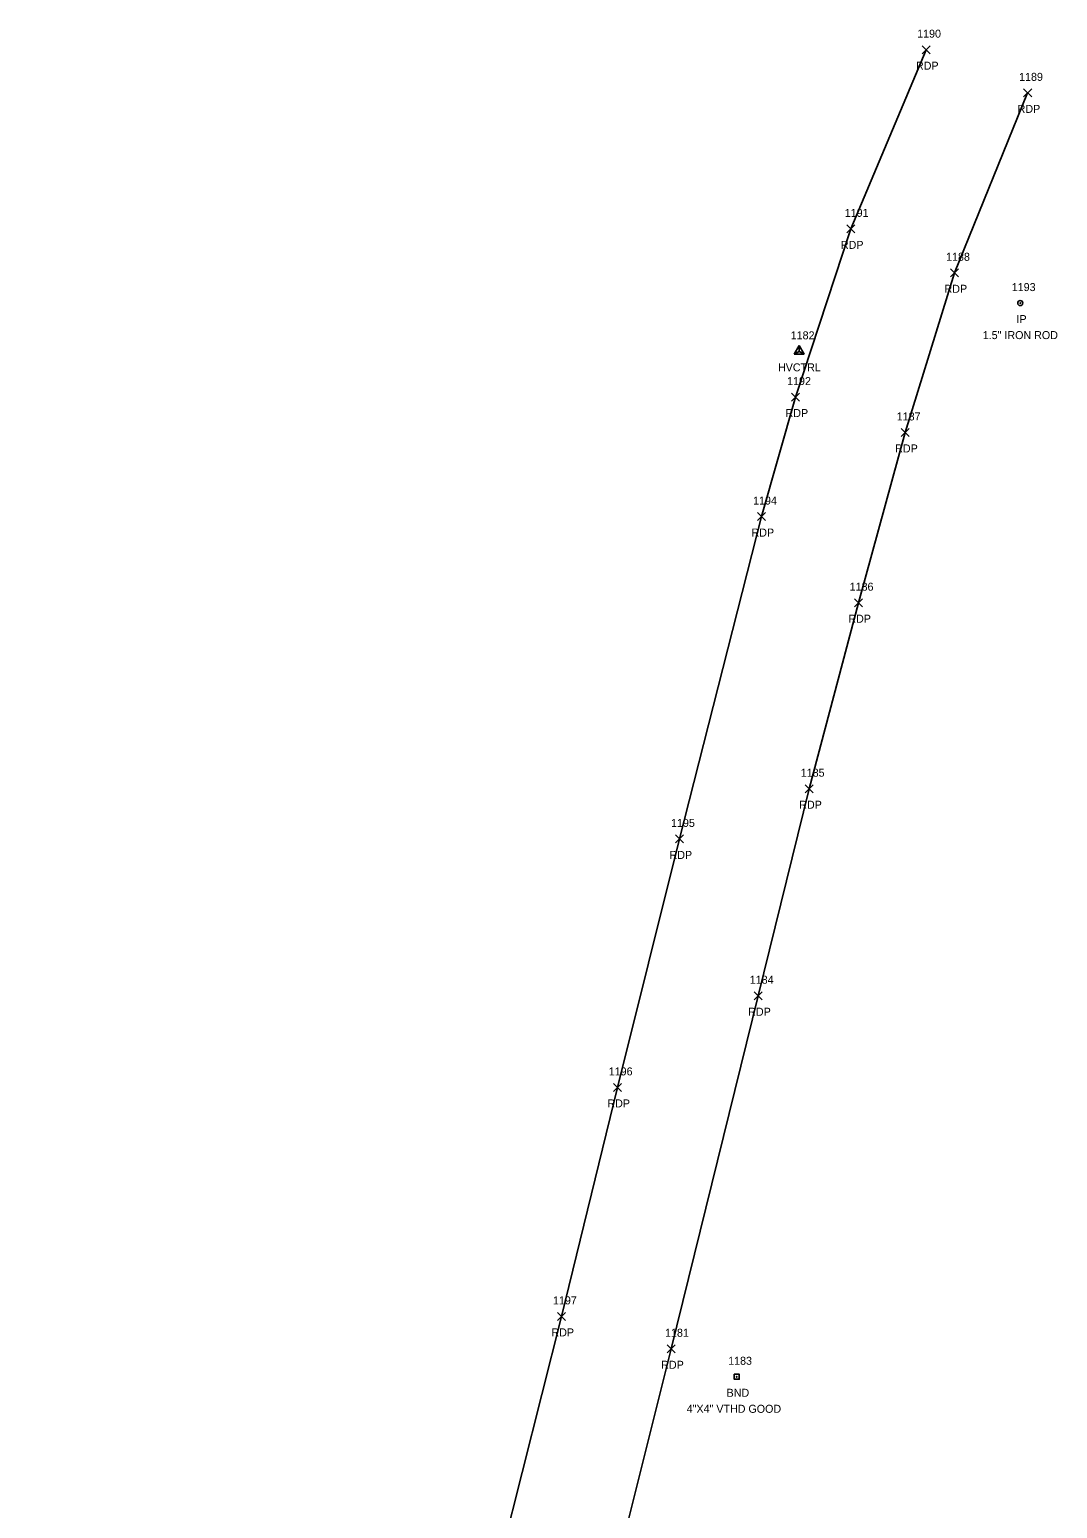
# Model space of a CAD drawing. Extents: x 1496556 to 1498241, y 599216 to 604470.
# Drawn here: x 1497984.6 to 1498241.4, y 604100.3 to 604469.9 of the extents above; entities that cross this region are included whole.
import ezdxf

# ---------------------------------------------------------------- set-up
doc = ezdxf.new("R2010")
doc.units = 0
for name, color, linetype in [('C_A', 7, 'Continuous'), ('C_I', 7, 'Continuous'), ('CPSM', 7, 'Continuous'), ('Level 18', 7, 'Continuous'), ('M_A', 7, 'Continuous'), ('M_C', 7, 'Continuous'), ('M_I', 7, 'Continuous'), ('MPIR', 7, 'Continuous'), ('P_A', 7, 'Continuous'), ('P_I', 7, 'Continuous'), ('P_TIC', 7, 'Continuous'), ('PET', 7, 'Continuous')]:
    doc.layers.add(name, color=color, linetype=linetype)

msp = doc.modelspace()

# ---------------------------------------------------------------- linework, layer by layer
at = {"layer": 'CPSM'}
for p, q in [((1498175.64, 604388.74), (1498176.89, 604390.91)), ((1498178.14, 604388.74), (1498176.89, 604390.91)), ((1498176.89, 604389.47), (1498176.89, 604390.91)), ((1498175.64, 604388.74), (1498176.89, 604389.47)), ((1498175.64, 604388.74), (1498178.14, 604388.74)), ((1498176.89, 604389.47), (1498176.89, 604389.47)), ((1498176.89, 604389.47), (1498178.14, 604388.74))]:
    msp.add_line(p, q, dxfattribs=at)
at = {"layer": 'Level 18'}
msp.add_lwpolyline([(1498160.64, 604133.86), (1498161.89, 604133.86), (1498161.89, 604132.61), (1498160.64, 604132.61)], close=True, dxfattribs=at)
msp.add_circle((1498161.26, 604133.23), 0.0833, dxfattribs=at)
at = {"layer": 'MPIR'}
for radius in [0.625, 0.0833]:
    msp.add_circle((1498232.14, 604401.53), radius, dxfattribs=at)
at = {"layer": 'P_TIC'}
for points in [[(1498207.59, 604463.85), (1498209.59, 604465.85)], [(1498209.59, 604463.85), (1498207.59, 604465.85)], [(1498232.98, 604453.06), (1498234.98, 604455.06)], [(1498234.98, 604453.06), (1498232.98, 604455.06)], [(1498188.82, 604419.08), (1498190.82, 604421.08)], [(1498190.82, 604419.08), (1498188.82, 604421.08)], [(1498214.73, 604408.1), (1498216.73, 604410.1)], [(1498216.73, 604408.1), (1498214.73, 604410.1)], [(1498175, 604377.05), (1498177, 604379.05)], [(1498177, 604377.05), (1498175, 604379.05)], [(1498202.39, 604368.21), (1498204.39, 604370.21)], [(1498204.39, 604368.21), (1498202.39, 604370.21)], [(1498166.5, 604347.18), (1498168.5, 604349.18)], [(1498168.5, 604347.18), (1498166.5, 604349.18)], [(1498190.68, 604325.66), (1498192.68, 604327.66)], [(1498192.68, 604325.66), (1498190.68, 604327.66)], [(1498178.41, 604279.18), (1498180.41, 604281.18)], [(1498180.41, 604279.18), (1498178.41, 604281.18)], [(1498146, 604266.63), (1498148, 604268.63)], [(1498148, 604266.63), (1498146, 604268.63)], [(1498165.67, 604227.45), (1498167.67, 604229.45)], [(1498167.67, 604227.45), (1498165.67, 604229.45)], [(1498130.48, 604204.54), (1498132.48, 604206.54)], [(1498132.48, 604204.54), (1498130.48, 604206.54)], [(1498116.5, 604147.32), (1498118.5, 604149.32)], [(1498118.5, 604147.32), (1498116.5, 604149.32)], [(1498143.93, 604139.23), (1498145.93, 604141.23)], [(1498145.93, 604139.23), (1498143.93, 604141.23)]]:
    msp.add_lwpolyline(points, dxfattribs=at)
at = {"layer": 'PET'}
for points in [[(1498208.59, 604464.85), (1498189.82, 604420.08), (1498176, 604378.05), (1498167.5, 604348.18), (1498147, 604267.63), (1498131.48, 604205.54), (1498117.5, 604148.32), (1498092.91, 604050.85), (1498077.58, 603989.22), (1498066.61, 603945.49), (1498055.36, 603901.89), (1498041.58, 603849.92), (1498027.4, 603802.6), (1498018.02, 603775.44), (1498003.54, 603741.59), (1497984.58, 603705.71)], [(1498024.5, 603720), (1498039.75, 603752.79), (1498057.17, 603800.42), (1498071.36, 603849.59), (1498083.48, 603896.2), (1498095.81, 603944.84), (1498120.84, 604043.96), (1498144.93, 604140.23), (1498166.67, 604228.45), (1498179.41, 604280.18), (1498191.68, 604326.66), (1498203.39, 604369.21), (1498215.73, 604409.1), (1498233.98, 604454.06)]]:
    msp.add_lwpolyline(points, dxfattribs=at)

# ---------------------------------------------------------------- texts
at = {"layer": 'C_A'}
msp.add_text('HVCTRL', height=2, dxfattribs=at).set_placement((1498171.59, 604384.47))
at = {"layer": 'C_I'}
msp.add_text('1182', height=2, dxfattribs=at).set_placement((1498174.77, 604392.47))
at = {"layer": 'M_A'}
for s, p in [('IP', (1498231.19, 604396.53)), ('BND', (1498158.75, 604128.23))]:
    msp.add_text(s, height=2, dxfattribs=at).set_placement(p)
at = {"layer": 'M_C'}
for s, p in [('1.5" IRON ROD', (1498222.76, 604392.53)), ('4"X4" VTHD GOOD', (1498148.78, 604124.23))]:
    msp.add_text(s, height=2, dxfattribs=at).set_placement(p)
at = {"layer": 'M_I'}
for s, p in [('1193', (1498230.01, 604404.53)), ('1183', (1498159.14, 604136.23))]:
    msp.add_text(s, height=2, dxfattribs=at).set_placement(p)
at = {"layer": 'P_A'}
for p in [(1498206.07, 604459.85), (1498231.47, 604449.06), (1498187.31, 604415.08), (1498213.21, 604404.1), (1498173.48, 604373.05), (1498200.88, 604364.21), (1498164.98, 604343.18), (1498189.17, 604321.66), (1498176.9, 604275.18), (1498144.49, 604262.63), (1498164.15, 604223.45), (1498128.96, 604200.54), (1498114.99, 604143.32), (1498142.41, 604135.23)]:
    msp.add_text('RDP', height=2, dxfattribs=at).set_placement(p)
at = {"layer": 'P_I'}
for s, p in [('1190', (1498206.37, 604467.85)), ('1189', (1498231.84, 604457.06)), ('1191', (1498188.27, 604423.08)), ('1188', (1498213.6, 604412.1)), ('1192', (1498173.87, 604381.05)), ('1187', (1498201.26, 604372.21)), ('1194', (1498165.37, 604351.18)), ('1186', (1498189.5, 604329.66)), ('1185', (1498177.28, 604283.18)), ('1195', (1498144.87, 604270.63)), ('1184', (1498164.54, 604231.45)), ('1196', (1498129.3, 604208.54)), ('1197', (1498115.37, 604151.32)), ('1181', (1498143.37, 604143.23))]:
    msp.add_text(s, height=2, dxfattribs=at).set_placement(p)

doc.saveas('drawing.dxf')
